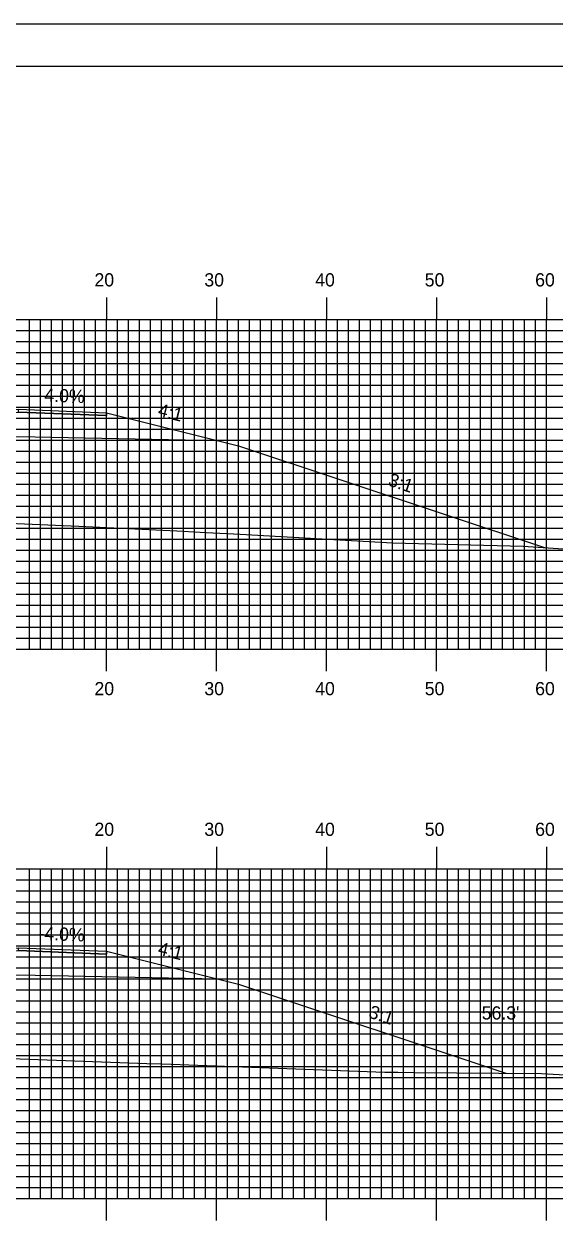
# Model space of a CAD drawing. Extents: x 1805471 to 1805814, y 442591 to 442811.
# Drawn here: x 1805649.2 to 1805697.5, y 442701.2 to 442810.5 of the extents above; entities that cross this region are included whole.
import ezdxf

# ---------------------------------------------------------------- set-up
doc = ezdxf.new("R2010")
doc.units = 0
for name, color, linetype in [('ANNOTATION', 7, 'Continuous'), ('BORDER', 7, 'Continuous'), ('D_Roadway_Centerline', 7, 'Continuous'), ('D_Roadway_Edge_Shoulder', 7, 'Continuous'), ('D_Roadway_SlopeLines', 7, 'Continuous'), ('D_Roadway_SubGrade', 7, 'Continuous'), ('D_Text_Standard', 7, 'Continuous'), ('H_V ANNOTATION', 7, 'Continuous'), ('MAJOR', 7, 'Continuous'), ('MINOR', 7, 'Continuous'), ('PLOT BOUNDARY', 7, 'Continuous'), ('S_Roadway_Centerline', 7, 'Continuous')]:
    doc.layers.add(name, color=color, linetype=linetype)

msp = doc.modelspace()

# ---------------------------------------------------------------- linework, layer by layer
at = {"layer": 'BORDER'}
msp.add_lwpolyline([(1805487.11, 442596.67), (1805807.11, 442596.67), (1805807.11, 442806.67), (1805487.11, 442806.67)], close=True, dxfattribs=at)
at = {"layer": 'D_Roadway_Centerline'}
for points in [[(1805589.04, 442767.68), (1805604.71, 442771.6), (1805606.53, 442772.05), (1805616.71, 442774.6), (1805624.71, 442774.92), (1805636.71, 442775.21), (1805648.71, 442775.49), (1805656.71, 442775.17), (1805666.88, 442772.63), (1805668.71, 442772.17), (1805696.54, 442762.9)], [(1805588.01, 442718.42), (1805604.71, 442722.6), (1805606.53, 442723.05), (1805616.71, 442725.6), (1805624.71, 442725.92), (1805636.71, 442726.21), (1805648.71, 442726.49), (1805656.71, 442726.17), (1805666.88, 442723.63), (1805668.71, 442723.17), (1805693.01, 442715.07)]]:
    msp.add_lwpolyline(points, dxfattribs=at)
at = {"layer": 'D_Roadway_Edge_Shoulder'}
for points in [[(1805648.71, 442775.49), (1805656.71, 442775.17), (1805656.71, 442774.92), (1805648.71, 442775.24)], [(1805648.71, 442726.49), (1805656.71, 442726.17), (1805656.71, 442725.92), (1805648.71, 442726.24)]]:
    msp.add_lwpolyline(points, close=True, dxfattribs=at)
at = {"layer": 'D_Roadway_SlopeLines'}
for points in [[(1805656.71, 442775.17), (1805668.71, 442772.17), (1805696.54, 442762.9)], [(1805656.71, 442726.17), (1805668.71, 442723.17), (1805693.01, 442715.07)]]:
    msp.add_lwpolyline(points, dxfattribs=at)
at = {"layer": 'D_Roadway_SubGrade'}
for points in [[(1805624.71, 442772.42), (1805606.53, 442772.05), (1805616.71, 442774.6), (1805616.71, 442774.35), (1805624.71, 442774.67), (1805636.71, 442774.96), (1805648.71, 442775.24), (1805656.71, 442774.92), (1805656.71, 442775.17), (1805666.88, 442772.63), (1805648.71, 442772.99), (1805636.71, 442772.71)], [(1805624.71, 442723.42), (1805606.53, 442723.05), (1805616.71, 442725.6), (1805616.71, 442725.35), (1805624.71, 442725.67), (1805636.71, 442725.96), (1805648.71, 442726.24), (1805656.71, 442725.92), (1805656.71, 442726.17), (1805666.88, 442723.63), (1805648.71, 442723.99), (1805636.71, 442723.71)]]:
    msp.add_lwpolyline(points, close=True, dxfattribs=at)
at = {"layer": 'MAJOR'}
for p, q in [((1805656.71, 442785.67), (1805656.71, 442783.67)), ((1805666.71, 442785.67), (1805666.71, 442783.67)), ((1805676.71, 442785.67), (1805676.71, 442783.67)), ((1805686.71, 442785.67), (1805686.71, 442783.67)), ((1805696.71, 442785.67), (1805696.71, 442783.67)), ((1805496.71, 442783.67), (1805776.71, 442783.67)), ((1805496.71, 442783.67), (1805776.71, 442783.67)), ((1805656.71, 442753.67), (1805656.71, 442783.67)), ((1805666.71, 442753.67), (1805666.71, 442783.67)), ((1805676.71, 442753.67), (1805676.71, 442783.67)), ((1805686.71, 442753.67), (1805686.71, 442783.67)), ((1805696.71, 442753.67), (1805696.71, 442783.67)), ((1805496.71, 442778.67), (1805776.71, 442778.67)), ((1805496.71, 442773.67), (1805776.71, 442773.67)), ((1805496.71, 442768.67), (1805776.71, 442768.67)), ((1805496.71, 442763.67), (1805776.71, 442763.67)), ((1805496.71, 442758.67), (1805776.71, 442758.67)), ((1805496.71, 442753.67), (1805776.71, 442753.67)), ((1805496.71, 442753.67), (1805776.71, 442753.67)), ((1805656.71, 442751.66), (1805656.71, 442753.67)), ((1805666.71, 442751.66), (1805666.71, 442753.67)), ((1805676.71, 442751.66), (1805676.71, 442753.67)), ((1805686.71, 442751.66), (1805686.71, 442753.67)), ((1805696.71, 442751.66), (1805696.71, 442753.67)), ((1805656.71, 442735.67), (1805656.71, 442733.67)), ((1805666.71, 442735.67), (1805666.71, 442733.67)), ((1805676.71, 442735.67), (1805676.71, 442733.67)), ((1805686.71, 442735.67), (1805686.71, 442733.67)), ((1805696.71, 442735.67), (1805696.71, 442733.67)), ((1805496.71, 442733.67), (1805776.71, 442733.67)), ((1805496.71, 442733.67), (1805776.71, 442733.67)), ((1805656.71, 442703.67), (1805656.71, 442733.67)), ((1805666.71, 442703.67), (1805666.71, 442733.67)), ((1805676.71, 442703.67), (1805676.71, 442733.67)), ((1805686.71, 442703.67), (1805686.71, 442733.67)), ((1805696.71, 442703.67), (1805696.71, 442733.67)), ((1805496.71, 442728.67), (1805776.71, 442728.67)), ((1805496.71, 442723.67), (1805776.71, 442723.67)), ((1805496.71, 442718.67), (1805776.71, 442718.67)), ((1805496.71, 442713.67), (1805776.71, 442713.67)), ((1805496.71, 442708.67), (1805776.71, 442708.67)), ((1805496.71, 442703.67), (1805776.71, 442703.67)), ((1805496.71, 442703.67), (1805776.71, 442703.67)), ((1805656.71, 442701.66), (1805656.71, 442703.67)), ((1805666.71, 442701.66), (1805666.71, 442703.67)), ((1805676.71, 442701.66), (1805676.71, 442703.67)), ((1805686.71, 442701.66), (1805686.71, 442703.67)), ((1805696.71, 442701.66), (1805696.71, 442703.67))]:
    msp.add_line(p, q, dxfattribs=at)
at = {"layer": 'MINOR'}
for p, q in [((1805649.71, 442753.67), (1805649.71, 442783.67)), ((1805650.71, 442753.67), (1805650.71, 442783.67)), ((1805651.71, 442753.67), (1805651.71, 442783.67)), ((1805652.71, 442753.67), (1805652.71, 442783.67)), ((1805653.71, 442753.67), (1805653.71, 442783.67)), ((1805654.71, 442753.67), (1805654.71, 442783.67)), ((1805655.71, 442753.67), (1805655.71, 442783.67)), ((1805657.71, 442753.67), (1805657.71, 442783.67)), ((1805658.71, 442753.67), (1805658.71, 442783.67)), ((1805659.71, 442753.67), (1805659.71, 442783.67)), ((1805660.71, 442753.67), (1805660.71, 442783.67)), ((1805661.71, 442753.67), (1805661.71, 442783.67)), ((1805662.71, 442753.67), (1805662.71, 442783.67)), ((1805663.71, 442753.67), (1805663.71, 442783.67)), ((1805664.71, 442753.67), (1805664.71, 442783.67)), ((1805665.71, 442753.67), (1805665.71, 442783.67)), ((1805667.71, 442753.67), (1805667.71, 442783.67)), ((1805668.71, 442753.67), (1805668.71, 442783.67)), ((1805669.71, 442753.67), (1805669.71, 442783.67)), ((1805670.71, 442753.67), (1805670.71, 442783.67)), ((1805671.71, 442753.67), (1805671.71, 442783.67)), ((1805672.71, 442753.67), (1805672.71, 442783.67)), ((1805673.71, 442753.67), (1805673.71, 442783.67)), ((1805674.71, 442753.67), (1805674.71, 442783.67)), ((1805675.71, 442753.67), (1805675.71, 442783.67)), ((1805677.71, 442753.67), (1805677.71, 442783.67)), ((1805678.71, 442753.67), (1805678.71, 442783.67)), ((1805679.71, 442753.67), (1805679.71, 442783.67)), ((1805680.71, 442753.67), (1805680.71, 442783.67)), ((1805681.71, 442753.67), (1805681.71, 442783.67)), ((1805682.71, 442753.67), (1805682.71, 442783.67)), ((1805683.71, 442753.67), (1805683.71, 442783.67)), ((1805684.71, 442753.67), (1805684.71, 442783.67)), ((1805685.71, 442753.67), (1805685.71, 442783.67)), ((1805687.71, 442753.67), (1805687.71, 442783.67)), ((1805688.71, 442753.67), (1805688.71, 442783.67)), ((1805689.71, 442753.67), (1805689.71, 442783.67)), ((1805690.71, 442753.67), (1805690.71, 442783.67)), ((1805691.71, 442753.67), (1805691.71, 442783.67)), ((1805692.71, 442753.67), (1805692.71, 442783.67)), ((1805693.71, 442753.67), (1805693.71, 442783.67)), ((1805694.71, 442753.67), (1805694.71, 442783.67)), ((1805695.71, 442753.67), (1805695.71, 442783.67)), ((1805496.71, 442782.67), (1805776.71, 442782.67)), ((1805496.71, 442781.67), (1805776.71, 442781.67)), ((1805496.71, 442780.67), (1805776.71, 442780.67)), ((1805496.71, 442779.67), (1805776.71, 442779.67)), ((1805496.71, 442777.67), (1805776.71, 442777.67)), ((1805496.71, 442776.67), (1805776.71, 442776.67)), ((1805496.71, 442775.67), (1805776.71, 442775.67)), ((1805496.71, 442774.67), (1805776.71, 442774.67)), ((1805496.71, 442772.67), (1805776.71, 442772.67)), ((1805496.71, 442771.67), (1805776.71, 442771.67)), ((1805496.71, 442770.67), (1805776.71, 442770.67)), ((1805496.71, 442769.67), (1805776.71, 442769.67)), ((1805496.71, 442767.67), (1805776.71, 442767.67)), ((1805496.71, 442766.67), (1805776.71, 442766.67)), ((1805496.71, 442765.67), (1805776.71, 442765.67)), ((1805496.71, 442764.67), (1805776.71, 442764.67)), ((1805496.71, 442762.67), (1805776.71, 442762.67)), ((1805496.71, 442761.67), (1805776.71, 442761.67)), ((1805496.71, 442760.67), (1805776.71, 442760.67)), ((1805496.71, 442759.67), (1805776.71, 442759.67)), ((1805496.71, 442757.67), (1805776.71, 442757.67)), ((1805496.71, 442756.67), (1805776.71, 442756.67)), ((1805496.71, 442755.67), (1805776.71, 442755.67)), ((1805496.71, 442754.67), (1805776.71, 442754.67)), ((1805649.71, 442703.67), (1805649.71, 442733.67)), ((1805650.71, 442703.67), (1805650.71, 442733.67)), ((1805651.71, 442703.67), (1805651.71, 442733.67)), ((1805652.71, 442703.67), (1805652.71, 442733.67)), ((1805653.71, 442703.67), (1805653.71, 442733.67)), ((1805654.71, 442703.67), (1805654.71, 442733.67)), ((1805655.71, 442703.67), (1805655.71, 442733.67)), ((1805657.71, 442703.67), (1805657.71, 442733.67)), ((1805658.71, 442703.67), (1805658.71, 442733.67)), ((1805659.71, 442703.67), (1805659.71, 442733.67)), ((1805660.71, 442703.67), (1805660.71, 442733.67)), ((1805661.71, 442703.67), (1805661.71, 442733.67)), ((1805662.71, 442703.67), (1805662.71, 442733.67)), ((1805663.71, 442703.67), (1805663.71, 442733.67)), ((1805664.71, 442703.67), (1805664.71, 442733.67)), ((1805665.71, 442703.67), (1805665.71, 442733.67)), ((1805667.71, 442703.67), (1805667.71, 442733.67)), ((1805668.71, 442703.67), (1805668.71, 442733.67)), ((1805669.71, 442703.67), (1805669.71, 442733.67)), ((1805670.71, 442703.67), (1805670.71, 442733.67)), ((1805671.71, 442703.67), (1805671.71, 442733.67)), ((1805672.71, 442703.67), (1805672.71, 442733.67)), ((1805673.71, 442703.67), (1805673.71, 442733.67)), ((1805674.71, 442703.67), (1805674.71, 442733.67)), ((1805675.71, 442703.67), (1805675.71, 442733.67)), ((1805677.71, 442703.67), (1805677.71, 442733.67)), ((1805678.71, 442703.67), (1805678.71, 442733.67)), ((1805679.71, 442703.67), (1805679.71, 442733.67)), ((1805680.71, 442703.67), (1805680.71, 442733.67)), ((1805681.71, 442703.67), (1805681.71, 442733.67)), ((1805682.71, 442703.67), (1805682.71, 442733.67)), ((1805683.71, 442703.67), (1805683.71, 442733.67)), ((1805684.71, 442703.67), (1805684.71, 442733.67)), ((1805685.71, 442703.67), (1805685.71, 442733.67)), ((1805687.71, 442703.67), (1805687.71, 442733.67)), ((1805688.71, 442703.67), (1805688.71, 442733.67)), ((1805689.71, 442703.67), (1805689.71, 442733.67)), ((1805690.71, 442703.67), (1805690.71, 442733.67)), ((1805691.71, 442703.67), (1805691.71, 442733.67)), ((1805692.71, 442703.67), (1805692.71, 442733.67)), ((1805693.71, 442703.67), (1805693.71, 442733.67)), ((1805694.71, 442703.67), (1805694.71, 442733.67)), ((1805695.71, 442703.67), (1805695.71, 442733.67)), ((1805496.71, 442732.67), (1805776.71, 442732.67)), ((1805496.71, 442731.67), (1805776.71, 442731.67)), ((1805496.71, 442730.67), (1805776.71, 442730.67)), ((1805496.71, 442729.67), (1805776.71, 442729.67)), ((1805496.71, 442727.67), (1805776.71, 442727.67)), ((1805496.71, 442726.67), (1805776.71, 442726.67)), ((1805496.71, 442725.67), (1805776.71, 442725.67)), ((1805496.71, 442724.67), (1805776.71, 442724.67)), ((1805496.71, 442722.67), (1805776.71, 442722.67)), ((1805496.71, 442721.67), (1805776.71, 442721.67)), ((1805496.71, 442720.67), (1805776.71, 442720.67)), ((1805496.71, 442719.67), (1805776.71, 442719.67)), ((1805496.71, 442717.67), (1805776.71, 442717.67)), ((1805496.71, 442716.67), (1805776.71, 442716.67)), ((1805496.71, 442715.67), (1805776.71, 442715.67)), ((1805496.71, 442714.67), (1805776.71, 442714.67)), ((1805496.71, 442712.67), (1805776.71, 442712.67)), ((1805496.71, 442711.67), (1805776.71, 442711.67)), ((1805496.71, 442710.67), (1805776.71, 442710.67)), ((1805496.71, 442709.67), (1805776.71, 442709.67)), ((1805496.71, 442707.67), (1805776.71, 442707.67)), ((1805496.71, 442706.67), (1805776.71, 442706.67)), ((1805496.71, 442705.67), (1805776.71, 442705.67)), ((1805496.71, 442704.67), (1805776.71, 442704.67))]:
    msp.add_line(p, q, dxfattribs=at)
at = {"layer": 'PLOT BOUNDARY'}
msp.add_lwpolyline([(1805470.92, 442590.55), (1805810.92, 442590.55), (1805810.92, 442810.55), (1805470.92, 442810.55)], close=True, dxfattribs=at)
at = {"layer": 'S_Roadway_Centerline'}
for points in [[(1805583.93, 442768.03), (1805591.82, 442767.49), (1805607.94, 442767.36), (1805618.17, 442766.41), (1805619.05, 442766.33), (1805620.02, 442766.29), (1805627.31, 442765.99), (1805639.82, 442765.54), (1805642.86, 442765.33), (1805654.18, 442764.85), (1805663.09, 442764.43), (1805665.75, 442764.29), (1805668.86, 442764.13), (1805682.7, 442763.34), (1805694.58, 442763.03), (1805705.07, 442762.34)], [(1805579.42, 442718.53), (1805597.92, 442718.31), (1805602.14, 442718.29), (1805617.95, 442717.73), (1805634.67, 442717.26), (1805640.65, 442716.98), (1805648.85, 442716.38), (1805660.37, 442715.96), (1805661.69, 442715.93), (1805662.57, 442715.89), (1805671.48, 442715.56), (1805682.02, 442715.18), (1805683.18, 442715.16), (1805684.66, 442715.15), (1805696.25, 442715.04), (1805705.33, 442714.54)]]:
    msp.add_lwpolyline(points, dxfattribs=at)

# ---------------------------------------------------------------- texts
at = {"layer": 'ANNOTATION'}
for s, rotation, p in [('-4.0%', 357.7094, (1805650.5, 442776.22)), ('4:1', 345.9638, (1805661.3, 442774.89)), ('3:1', 341.5652, (1805682.23, 442768.58)), ('-4.0%', 357.7094, (1805650.5, 442727.22)), ('4:1', 345.9638, (1805661.3, 442725.89)), ('3:1', 341.5652, (1805680.46, 442720.16))]:
    msp.add_text(s, height=1.2, rotation=rotation, dxfattribs=at).set_placement(p)
at = {"layer": 'D_Text_Standard'}
msp.add_text("56.3'", height=1.2, dxfattribs=at).set_placement((1805690.82, 442719.96))
at = {"layer": 'H_V ANNOTATION'}
for s, p in [('20', (1805655.61, 442786.67)), ('30', (1805665.6, 442786.67)), ('40', (1805675.68, 442786.67)), ('50', (1805685.64, 442786.67)), ('60', (1805695.68, 442786.67)), ('20', (1805655.61, 442749.47)), ('30', (1805665.6, 442749.47)), ('40', (1805675.68, 442749.47)), ('50', (1805685.64, 442749.47)), ('60', (1805695.68, 442749.47)), ('20', (1805655.61, 442736.67)), ('30', (1805665.6, 442736.67)), ('40', (1805675.68, 442736.67)), ('50', (1805685.64, 442736.67)), ('60', (1805695.68, 442736.67))]:
    msp.add_text(s, height=1.2, dxfattribs=at).set_placement(p)

doc.saveas('drawing.dxf')
